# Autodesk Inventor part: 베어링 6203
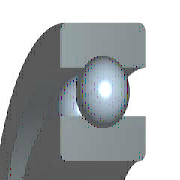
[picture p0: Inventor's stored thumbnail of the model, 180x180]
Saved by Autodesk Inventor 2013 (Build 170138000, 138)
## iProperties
IsCustomPart: 0
Created: 2018-09
Part Number: 베어링 6203
Material: 스테인리스강
Description: 깊은 그루브 볼 베어링
Document SubType Name: Modeling
Standard: KS B 2023
Standards Organization: KS
Language: ko-KR
Size Designation: 6203 - 17 x 40 x 12
Categories: <MemberInstance><Categories><Category DisplayName="샤프트 부품" InternalName="7f7aeb1f-a693-4053-b835-cee3144e0d98" Mnemonic="SHFT"><Category DisplayName="베어링" Inter
Density: 8.08 g/cm^3
Mass: 66.7997 g
Surface Area: 64.3582 cm^2
Volume: 8.26729 cm^3
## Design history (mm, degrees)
sketch "스케치" dims "d0" = 5.98 (= -0.26 x WD + 0.26 x BD)
  geometry: L1 (3.01, 14.25)-(8.99, 14.25); L2 (6, 14.25)-(6, 11.26); L3 (6, 14.25)-(6, 17.24); L4 (3.778, 12.249)-(0, 12.249); L5 (0, 8.5)-(12, 8.5); L6 (3.778, 16.251)-(0, 16.251); L7 (0, 20)-(12, 20); L8 (12, 8.5)-(12, 12.249); L9 (8.222, 12.249)-(12, 12.249); L10 (8.222, 16.251)-(12, 16.251); L11 (12, 20)-(12, 16.251); L12 (-1.4, 0)-(8.4, 0) reference; L13 (0, -0.3)-(0, 5.3) reference
  constraints: 22 end point, 4 point on line, 2 collinear, 2 perpendicular, 2 symmetric about line, 1 midpoint, 1 parallel, 14 other
  dimensions: "d9" = 17 diameter of L5 L12 (= WD); "d11" = 40 diameter of L7 L12 (= BD); "d12" = 12 distance between parallel lines of L8 L13 (= KB); "d13" = 24.498 diameter of L9 L12 (= 0.326 x BD + 0.674 x WD)
revolve "본체" stored, may be unused: angle "d6" = 90 deg
revolve "볼" stored, may be unused: angle "d7" = 90 deg
pattern_circular "IDS_ARRAYBALL[SIMPL:T]" dims angle "d3" = 360 deg
body "Solid1"
fillet "모깎기1" dims "d1" = 0.6 (= KRS)
other parameters: "WD" = 17 [user parameter; used in 5 equation terms], "BD" = 40 [user parameter; used in 5 equation terms], "KB" = 12 [user parameter; used in 1 equation term], "KRS" = 0.6 [user parameter; used in 1 equation term], "d4" = 0, "d5" = 0, "d8" = 0, "d14" = 0, "d15" = 0, "BBA" = 0 [user parameter], "BC0" = 4750000 [user parameter], "BC" = 9560000 [user parameter], "WR" = 8.5 (= 0.5 x WD) [user parameter]
